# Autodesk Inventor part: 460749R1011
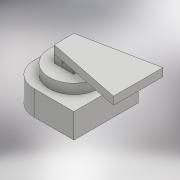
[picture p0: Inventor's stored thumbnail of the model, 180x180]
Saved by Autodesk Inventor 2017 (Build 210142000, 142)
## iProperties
Created: 2016-07
Part Number: 460749R1011
Material: Generic
Document SubType Name: Modeling
Designer: Polytech
Density: 1 g/cm^3
Appearance: Default
Author: Polytech
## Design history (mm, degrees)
sketch "Sketch1"
  geometry: C1 r 23 at (0, 0); 1 further point
  constraints: 1 centre point, 1 coincident
  dimensions: "d0" = 46 diameter of C1
extrude "Extrusion1" new body sketch "Sketch1" distance "d1" = 18; taper "d2" = 0 deg
sketch "Sketch2"
  geometry: L1 (-11.75, 48.75)-(48.75, 48.75); L2 (48.75, 48.75)-(48.75, -48.75); L3 (48.75, -48.75)-(-11.75, -48.75); L4 (-48.75, -11.75)-(-48.75, 11.75); L5 (-48.75, 48.75)-(48.75, -48.75); L6 (48.75, 48.75)-(-48.75, -48.75); A1 r 37 centre (-11.75, 11.75) between (-11.75, 48.75) and (-48.75, 11.75); A2 r 37 centre (-11.75, -11.75) between (-48.75, -11.75) and (-11.75, -48.75); 1 further point
  constraints: 12 end point, 4 point on circle, 4 point on line, 4 tangent, 2 centre point, 2 midpoint, 2 parallel, 1 equal radius, 1 horizontal, 1 perpendicular
  dimensions: "d3" = 97.5 distance of L2.end L6.end; "d4" = 97.5 distance of L1.end L2.end; "d5" = 37 radius of A1
extrude "Extrusion2" join sketch "Sketch2" distance "d6" = 37.5; taper "d7" = 0 deg
sketch "Sketch3"
  geometry: C1 r 37.5 at (0, 0); 1 further point
  constraints: 1 centre point, 1 coincident
  dimensions: "d8" = 75 diameter of C1
extrude "Extrusion3" join sketch "Sketch3" distance "d9" = 15; taper "d10" = 0 deg
sketch "Sketch4"
  geometry: L1 (-15, 15)-(15, 15); L2 (15, 15)-(15, -15); L3 (15, -15)-(-15, -15); L4 (-15, -15)-(-15, 15); L5 (-15, 15)-(15, -15); L6 (15, 15)-(-15, -15); L7 (-15, 6)-(15, 6); L8 (15, 6)-(15, -6); L9 (15, -6)-(-15, -6); L10 (-15, -6)-(-15, 6); L11 (-15, 6)-(15, -6); L12 (15, 6)-(-15, -6); 1 further point
  constraints: 24 end point, 4 midpoint, 4 parallel, 2 horizontal, 2 perpendicular
  dimensions: "d11" = 30 distance of L2.end L3.end; "d12" = 30 distance of L1.end L2.end; "d13" = 30 distance of L8.end L9.end; "d14" = 12 distance of L7.end L8.end
extrude "Extrusion4" join sketch "Sketch4" distance "d15" = 12; taper "d16" = 0 deg
sketch "Sketch5"
  geometry: L1 (52.5, 0)-(-22.5, 0) reference; C1 r 3 at (15, 6); 1 further point
  constraints: 1 centre point, 1 vertical alignment
  dimensions: "d17" = 6 diameter of C1; "d18" = 6 distance from line of L1 C1.centre
extrude "Extrusion5" cut sketch "Sketch5" stored distance "d19" = 12; taper "d20" = 0 deg
sketch "Sketch6"
  geometry: L1 (-15, 15)-(-15, -15); L2 (-15, -15)-(97.5, -37.5); L3 (97.5, -37.5)-(97.5, 37.5); L4 (97.5, 37.5)-(-15, 15); 4 further points
  constraints: 8 end point, 2 coincident, 1 horizontal alignment, 1 midpoint, 1 parallel, 1 vertical
  dimensions: "d21" = 97.5 distance from line of L3 point (0, 0); "d22" = 75 distance of L2.end L3.end
extrude "Extrusion6" join sketch "Sketch6" distance "d23" = 12; taper "d24" = 0 deg
sketch "Sketch7"
  geometry: C1 r 23 at (0, 0); 1 further point
  constraints: 1 centre point, 1 coincident
  dimensions: "d25" = 46 diameter of C1
extrude "Extrusion7" cut sketch "Sketch7" distance "d26" = 24.5; taper "d27" = 0 deg
body "Solid1"
